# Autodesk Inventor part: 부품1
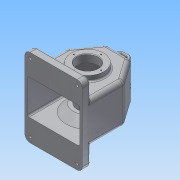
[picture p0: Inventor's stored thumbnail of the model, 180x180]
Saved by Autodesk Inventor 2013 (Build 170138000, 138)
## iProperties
Created: 2016-12
Part Number: 부품1
Material: 알루미늄 6061
Document SubType Name: Modeling
Designer: Administrator
Density: 2.71 g/cm^3
Mass: 1071.7 g
Surface Area: 1151.31 cm^2
Volume: 395.461 cm^3
Author: Administrator
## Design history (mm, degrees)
sketch "스케치1"
  geometry: L1 (-55, 0)-(55, 0); L2 (55, 0)-(55, 80); L3 (55, 80)-(-55, 80); L4 (-55, 80)-(-55, 0); 2 further points
  constraints: 8 end point, 2 parallel, 1 coincident, 1 horizontal, 1 midpoint, 1 perpendicular
  dimensions: "d0" = 110 distance of L3.end L2.end; "d1" = 80 distance of L2.end L1.end
extrude "돌출1" new body sketch "스케치1" stored distance "d2" = 77; taper "d3" = 0 deg
sketch "스케치2"
  geometry: L1 (-55, 80)-(55, 80); L2 (23.491, 125)-(-23.491, 125); L3 (-55, 80)-(55, 80) reference; L4 (-55, 80)-(-23.491, 125); L5 (55, 80)-(23.491, 125); 2 further points
  constraints: 8 end point, 2 midpoint, 1 horizontal, 1 parallel
  dimensions: "d6" = 55 deg angle of L1 L4; "d7" = 55 deg angle of L1 L5; "d8" = 45 vertical distance of L1.end L2.start; "d9" = 90.10672 distance from line of L1.end L4
extrude "돌출2" join sketch "스케치2" stored distance "d10" = 77; taper "d11" = 0 deg
fillet "모깎기1" dims "d12" = 10
fillet "모깎기2" dims "d13" = 8
feature "쉘1" dims "d14" = 5
sketch "스케치3"
  geometry: L1 (-47, -38.5)-(47, -38.5); L2 (55, -30.5)-(55, 30.5); L3 (47, 38.5)-(-47, 38.5); L4 (-55, 30.5)-(-55, -30.5); L5 (-55, -38.5)-(55, 38.5); L6 (55, -38.5)-(-55, 38.5); L7 (-55, 75)-(55, 75); L8 (55, 75)-(55, -75); L9 (55, -75)-(-55, -75); L10 (-55, -75)-(-55, 75); L11 (-55, 75)-(55, -75); L12 (55, 75)-(-55, -75); A1 r 8 centre (47, 30.5) between (55, 30.5) and (47, 38.5); A2 r 8 centre (47, -30.5) between (47, -38.5) and (55, -30.5); A3 r 8 centre (-47, -30.5) between (-55, -30.5) and (-47, -38.5); A4 r 8 centre (-47, 30.5) between (-47, 38.5) and (-55, 30.5); 3 further points
  constraints: 24 end point, 8 point on circle, 8 point on line, 8 tangent, 5 midpoint, 4 centre point, 4 parallel, 3 equal radius, 2 horizontal, 2 perpendicular, 1 coincident
  dimensions: "d15" = 110 distance of L6.end L5.end; "d16" = 77 distance of L5.end L6.start; "d17" = 8 radius of A1; "d18" = 110 distance of L8.end L9.end; "d19" = 150 distance of L7.end L8.end
extrude "돌출3" join sketch "스케치3" distance "d20" = 15; taper "d21" = 0 deg
fillet "모깎기3" dims "d22" = 10
sketch "스케치4"
  geometry: L1 (-47, 15)-(-47, 76.847) reference; L2 (0, 0)-(0, 65); C1 r 37.5 at (0, 65)
  constraints: 2 end point, 1 centre point, 1 coincident, 1 parallel
  dimensions: "d23" = 65 distance of L2.start L2.end; "d24" = 75 diameter of C1
extrude "돌출4" join sketch "스케치4" distance "d25" = 5; taper "d26" = 0 deg
sketch "스케치5"
  geometry: C1 r 37.5 at (0, 0) reference; C2 r 20 at (0, 0); 1 further point
  constraints: 1 centre point, 1 coincident
  dimensions: "d27" = 40 diameter of C2
extrude "돌출5" cut sketch "스케치5" distance "d28" = 100; taper "d29" = 0 deg
sketch "스케치6"
  geometry: C1 r 20 at (0, 65) reference; C2 r 31 at (0, 65); 1 further point
  constraints: 1 centre point, 1 coincident
  dimensions: "d30" = 62 diameter of C2
extrude "돌출6" join sketch "스케치6" distance "d31" = 10; taper "d32" = 0 deg
sketch "스케치7"
  geometry: L1 (0, 0)-(65, 0); L2 (65, 0)-(65, -33.5); L3 (65, -33.5)-(106, -33.5); L4 (92, -19.5)-(65, -19.5); L5 (92, -19.5)-(106, -33.5); L6 (65, -19.5)-(65, -33.5)
  constraints: 12 end point, 2 perpendicular, 1 collinear, 1 horizontal, 1 point on line
  dimensions: "d33" = 65 distance of L1.start L1.end; "d34" = 33.5 distance of L1.end L2.end; "d40" = 135 deg angle of L5 L4; "d41" = 14 distance between parallel lines of L3 L4; "d42" = 41 distance of L2.end L3.end
revolve "회전1" sketch "스케치7" stored, may be unused: angle "d43" = 90 deg
sketch "스케치8"
  geometry: C1 r 20 at (0, 0) reference; C2 r 20 at (0, 0); 1 further point
  constraints: 1 centre point, 1 coincident
  dimensions: "d44" = 40 diameter of C2
extrude "돌출7" cut sketch "스케치8" distance "d45" = 20; taper "d46" = 0 deg
sketch "스케치9"
  geometry: C1 r 20 at (0, 0) reference; 2 further points
  dimensions: "d47" = 29 distance of C1.centre point (0, 29); "d48" = 0 horizontal distance of C1.centre point (0, 29)
hole "구멍1" sketch "스케치9" at (0, 29) diameter "d49" = 2.459; stored, may be unused: countersink angle "d53" = 90 deg, drill point angle "d55" = 118 deg; dims "d50" = 6, "d51" = 4, "d52" = 2, "d54" = 8
sketch "스케치10"
  geometry: C1 r 20 at (0, 0) reference; 2 further points
  dimensions: "d59" = 26 distance of C1.centre point (0, 26); "d60" = 0 horizontal distance of C1.centre point (0, 26)
hole "구멍2" sketch "스케치10" at (0, 26) diameter "d61" = 2.459; stored, may be unused: countersink angle "d65" = 90 deg, drill point angle "d67" = 118 deg; dims "d62" = 6, "d63" = 4, "d64" = 2, "d66" = 8
node "작업 평면1"
sketch "스케치11"
  geometry: L1 (-4.5, 140)-(4.5, 140); L2 (12.5, 132)-(12.5, 125); L3 (-12.5, 125)-(-12.5, 132); L4 (-12.5, 140)-(12.5, 125); L5 (12.5, 140)-(-12.5, 125); L6 (55, 0)-(50, 0) reference; L7 (50, 0)-(50, 76.847) reference; L8 (49.096, 79.715)-(22.381, 117.868) reference; L9 (18.285, 120)-(-18.285, 120) reference; L10 (-22.381, 117.868)-(-49.096, 79.715) reference; L11 (-50, 76.847)-(-50, 0) reference; L12 (-50, 0)-(-55, 0) reference; L13 (-55, 0)-(-55, 76.847) reference; L14 (-53.192, 82.583)-(-26.477, 120.736) reference; L15 (-18.285, 125)-(18.285, 125) reference; L16 (26.477, 120.736)-(53.192, 82.583) reference; L17 (55, 76.847)-(55, 0) reference; L18 (7.5, 125)-(7.5, 132); L19 (4.5, 135)-(-4.5, 135); L20 (-7.5, 132)-(-7.5, 125); L21 (12.5, 125)-(7.5, 125); L22 (-7.5, 125)-(-12.5, 125); A1 r 5 centre (45, 76.847) between (50, 76.847) and (49.096, 79.715) reference; A2 r 5 centre (18.285, 115) between (22.381, 117.868) and (18.285, 120) reference; A3 r 5 centre (-18.285, 115) between (-18.285, 120) and (-22.381, 117.868) reference; A4 r 5 centre (-45, 76.847) between (-49.096, 79.715) and (-50, 76.847) reference; A5 r 10 centre (-45, 76.847) between (-53.192, 82.583) and (-55, 76.847) reference; A6 r 10 centre (-18.285, 115) between (-18.285, 125) and (-26.477, 120.736) reference; A7 r 10 centre (18.285, 115) between (26.477, 120.736) and (18.285, 125) reference; A8 r 10 centre (45, 76.847) between (55, 76.847) and (53.192, 82.583) reference; A9 r 8 centre (-4.5, 132) between (-4.5, 140) and (-12.5, 132); A10 r 8 centre (4.5, 132) between (12.5, 132) and (4.5, 140); A11 r 3 centre (4.5, 132) between (7.5, 132) and (4.5, 135); A12 r 3 centre (-4.5, 132) between (-4.5, 135) and (-7.5, 132); 3 further points
  constraints: 20 end point, 8 point on circle, 4 centre point, 4 parallel, 4 point on line, 4 tangent, 3 midpoint, 2 perpendicular, 1 equal radius, 1 horizontal, 4 other
  dimensions: "d72" = 25 distance of L2.end L3.start; "d73" = 15 distance of L5.start L2.end; "d74" = 8 radius of A9; "d75" = 5 distance between parallel lines of L2 L18; "d76" = 15 distance of L18.start L20.end; "d77" = 42.5 distance between parallel lines of L17 L2; "d78" = 125 distance between parallel lines of L6 L21
extrude "돌출8" join sketch "스케치11" distance "d79" = 8; taper "d80" = 0 deg
sketch "스케치12"
  geometry: A1 r 10 centre (-45, 65) between (-45, 75) and (-55, 65) reference; A2 r 10 centre (45, 65) between (55, 65) and (45, 75) reference; 3 further points
  constraints: 2 coincident
hole "구멍3" sketch "스케치12" at (-45, 65), (45, 65) diameter "d81" = 5; stored, may be unused: countersink angle "d85" = 90 deg, drill point angle "d87" = 118 deg; dims "d82" = 6, "d83" = 12, "d84" = 5, "d86" = 8
sketch "스케치13"
  geometry: A1 r 10 centre (-45, -65) between (-55, -65) and (-45, -75) reference; A2 r 10 centre (45, -65) between (45, -75) and (55, -65) reference; 3 further points
  constraints: 2 coincident
hole "구멍4" sketch "스케치13" at (-45, -65), (45, -65) diameter "d88" = 5; stored, may be unused: countersink angle "d92" = 90 deg, drill point angle "d94" = 118 deg; dims "d89" = 6, "d90" = 12, "d91" = 5, "d93" = 8
chamfer "모따기1" distance "d95" = 1; stored, may be unused: second distance "d96" = 2, angle "d97" = 45 deg
fillet "모깎기4" dims "d98" = 3
fillet "모깎기5" dims "d99" = 3
sketch "스케치14"
  geometry: L1 (-8, 0)-(-8, -58.847) reference; 2 further points
  constraints: 1 other
  dimensions: "d100" = 45 distance of point (30.5, -76.847) point (30.5, -31.847); "d101" = 38.5 distance from line of L1 point (30.5, -31.847)
feature "엠보싱1" sketch "스케치14" dims "d13" = 8, "d102" = 0.5, "d103" = 0
fillet "모깎기6" dims "d104" = 1
fillet "모깎기7" dims "d105" = 1
fillet "모깎기8" dims "d106" = 1
fillet "모깎기9" dims "d107" = 1
fillet "모깎기10" dims "d108" = 1
node "솔리드1"
pattern_circular "원형 패턴1" dims angle "d57" = 360 deg
pattern_circular "원형 패턴2" dims angle "d69" = 360 deg
mirror "대칭1"
mirror "대칭2"
node "작업 평면2"
node "절단 모서리 투영1"
other parameters: "d71" = -18
